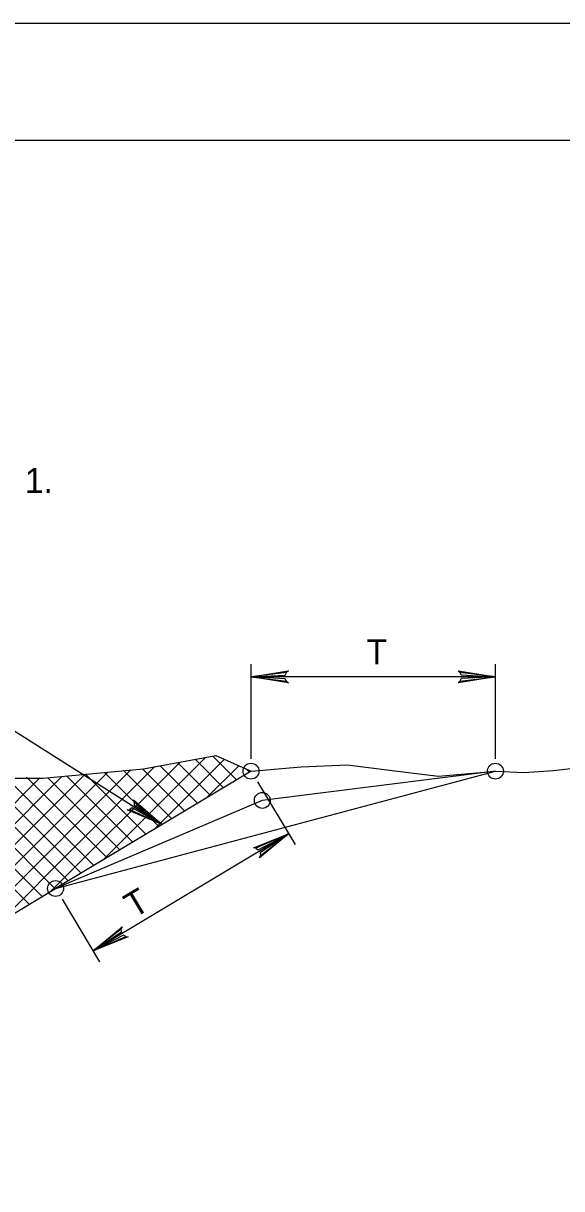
# Model space of a CAD drawing. Extents: x 240 to 1147, y 662 to 1256.
# Drawn here: x 896.9 to 965.7, y 1106.9 to 1256 of the extents above; entities that cross this region are included whole.
import ezdxf

# ---------------------------------------------------------------- set-up
doc = ezdxf.new("R2010")
doc.units = 0
for name, color, linetype in [('1', 7, 'Continuous'), ('2', 7, 'Continuous'), ('3', 7, 'Continuous'), ('PLT-BNDY', 7, 'Continuous')]:
    doc.layers.add(name, color=color, linetype=linetype)

msp = doc.modelspace()

# ---------------------------------------------------------------- linework, layer by layer
at = {"layer": '1'}
for points in [[(1065.4425, 677.018625), (1065.4425, 1241.018625), (279.4425, 1241.018625), (279.4425, 677.018625), (1065.4425, 677.018625), (1065.4425, 703.377625), (865.4425, 703.377625), (865.4425, 768.055125), (1065.4425, 768.055125), (1065.4425, 797.018625), (865.4425, 797.018625), (865.4425, 677.018625), (944.244, 677.018625), (944.244, 703.377625), (944.244, 677.018625), (1021.244, 677.018625), (1021.244, 703.377625), (1021.244, 691.061125), (1065.4425, 691.061125)], [(930.52475, 1171.840625), (930.356, 1172.167625), (925.98525, 1172.409375), (930.52475, 1171.840625), (930.758, 1171.640625), (925.98525, 1172.409375), (930.35175, 1172.626125), (930.51225, 1172.951125), (925.98525, 1172.409375), (930.758, 1173.167625), (930.51225, 1172.951125)], [(952.6935, 1172.980125), (952.86225, 1172.651125), (957.23525, 1172.409375), (952.6935, 1172.980125), (952.46025, 1173.180125), (957.23525, 1172.409375), (952.8665, 1172.194875), (952.706, 1171.867625), (957.23525, 1172.409375), (952.46025, 1171.651125), (952.706, 1171.867625)], [(911.052, 1156.386375), (911.022, 1156.017625), (914.608, 1153.505125), (911.052, 1156.386375), (910.95825, 1156.677875), (914.608, 1153.505125), (910.78475, 1155.626125), (910.477, 1155.435875), (914.608, 1153.505125), (910.15225, 1155.380375), (910.477, 1155.435875)], [(926.59775, 1150.484375), (926.91025, 1150.290625), (930.783, 1152.332375), (926.59775, 1150.484375), (926.2955, 1150.536375), (930.783, 1152.332375), (927.14975, 1149.898875), (927.179, 1149.538625), (930.783, 1152.332375), (927.081, 1149.226125), (927.179, 1149.538625)], [(909.9705, 1139.180125), (909.656, 1139.373875), (905.783, 1137.332375), (909.9705, 1139.180125), (910.27275, 1139.128125), (905.783, 1137.332375), (909.4185, 1139.763625), (909.38725, 1140.126125), (905.783, 1137.332375), (909.48725, 1140.438625), (909.38725, 1140.126125)]]:
    msp.add_lwpolyline(points, dxfattribs=at)
at = {"layer": '2'}
for p, q in [((881.8395, 1174.249125), (914.608, 1153.505125)), ((925.98525, 1161.930125), (925.98525, 1174.009375)), ((957.23525, 1161.930125), (957.23525, 1174.009375)), ((957.23525, 1172.409375), (925.98525, 1172.409375)), ((907.0165, 1148.951125), (920.156, 1162.090625)), ((913.6455, 1152.928125), (922.56425, 1161.846875)), ((922.4665, 1158.221875), (918.83725, 1161.851125)), ((924.12475, 1159.215625), (921.081, 1162.257375)), ((897.608, 1143.305125), (879.81425, 1161.096875)), ((880.49975, 1133.040625), (907.683, 1160.223875)), ((899.26425, 1144.298875), (883.056, 1160.509375)), ((900.92275, 1145.294875), (886.106, 1160.109375)), ((887.129, 1137.017625), (910.61025, 1160.498875)), ((893.758, 1140.994875), (913.67675, 1160.913625)), ((900.38725, 1144.973875), (916.9165, 1161.501125)), ((900.98525, 1145.330125), (957.23525, 1160.330125)), ((925.98525, 1160.330125), (900.98525, 1145.330125)), ((914.181, 1153.248875), (907.2455, 1160.182375)), ((915.83725, 1154.242625), (909.6705, 1160.409375)), ((917.4955, 1155.238625), (912.0955, 1160.636375)), ((919.15175, 1156.232375), (914.34975, 1161.036375)), ((920.81025, 1157.226125), (916.5935, 1161.442625)), ((920.27475, 1156.905125), (924.40175, 1161.032375)), ((925.781, 1160.209375), (925.40175, 1160.588625)), ((957.23525, 1160.330125), (927.42275, 1156.594875)), ((860.61225, 1121.107375), (898.97475, 1159.469875)), ((867.2415, 1125.086375), (901.831, 1159.676125)), ((873.8705, 1129.063625), (904.758, 1159.948875)), ((902.579, 1146.288625), (888.8955, 1159.971875)), ((904.23725, 1147.282375), (891.68725, 1159.832375)), ((905.8935, 1148.278125), (894.47675, 1159.692625)), ((907.55175, 1149.271875), (897.2685, 1159.555125)), ((909.208, 1150.265625), (899.97275, 1159.501125)), ((910.8665, 1151.259375), (902.39775, 1159.728125)), ((912.52275, 1152.255125), (904.82275, 1159.955125)), ((926.808, 1158.959375), (931.606, 1150.959375)), ((927.42275, 1156.594875), (900.98525, 1145.330125)), ((930.783, 1152.332375), (905.783, 1137.332375)), ((860.254, 1120.892625), (900.98525, 1145.330125)), ((901.808, 1143.959375), (906.606, 1135.959375))]:
    msp.add_line(p, q, dxfattribs=at)
for points in [[(759.52275, 1160.330125), (764.156, 1160.167625), (769.37675, 1160.167625), (776.4955, 1159.688625), (783.37675, 1158.728125), (793.3415, 1158.728125), (799.03725, 1158.009375), (807.3415, 1158.488625), (814.22275, 1158.728125), (820.3915, 1158.488625), (828.933, 1158.248875), (836.52675, 1159.688625), (843.1705, 1159.928125), (851.47475, 1159.448875), (864.05175, 1163.528125), (875.679, 1161.848875), (884.933, 1160.167625), (894.89775, 1159.448875), (899.406, 1159.448875), (912.2185, 1160.648875), (921.47275, 1162.328125), (925.98525, 1160.330125)], [(925.98525, 1160.330125), (932.38725, 1160.888625), (938.3205, 1161.128125), (944.01425, 1160.409375), (949.94775, 1159.688625), (957.23525, 1160.330125), (960.86225, 1160.167625), (964.658, 1160.409375), (968.6915, 1160.888625), (971.77675, 1161.367625), (975.33525, 1162.809375)]]:
    msp.add_lwpolyline(points, dxfattribs=at)
for centre in [(925.984167, 1160.331208), (957.234167, 1160.331208), (927.422667, 1156.594958), (900.984167, 1145.331208)]:
    msp.add_circle(centre, 1.015435, dxfattribs=at)
at = {"layer": 'PLT-BNDY'}
msp.add_lwpolyline([(240.4425, 1256.018625), (1081.4425, 1256.018625), (1081.4425, 662.018625), (240.4425, 662.018625)], close=True, dxfattribs=at)

# ---------------------------------------------------------------- texts
at = {"layer": '2'}
msp.add_text('T', height=3.199988, dxfattribs=at).set_placement((940.754, 1174.009375))
msp.add_text('T', height=3.199985, rotation=30.96375556, dxfattribs=at).set_placement((911.0205, 1141.453125))
at = {"layer": '3'}
msp.add_text('FOR BOTTOM WIDTHS > 2.5 m (8\'-0"), EXCAVATION IS CLASS 1.', height=3.1999875, dxfattribs=at).set_placement((770.72675, 1195.919913))

doc.saveas('drawing.dxf')
